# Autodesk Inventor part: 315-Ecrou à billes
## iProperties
Author: Philippe
Created: 2001-12
Part Number: 315-Ecrou à billes
Material: Par défaut
Document SubType Name: Modélisation
Designer: Philippe
Control State: 0
Master: False
Checked Out: False
PropertySet Name: Design Tracking Control
Shininess: 20.0
Angle Display Precision: 2
Document Length Units: 11269
Document Angle Units: 11283
Document Time Units: 11279
Document Mass Units: 11290
Document Length Units Precision: 3
Document Angle Units Precision: 2
Compacted: False
PropertySet Name: _Private Model Information
Density: 0.0
Volumn: 0.0
Area: 0.0
PropertySet Name: Model Information
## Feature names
1. Révolution1 [Revolution]
2. Chanfrein1 [Chamfer]
3. Chanfrein2 [Chamfer]
